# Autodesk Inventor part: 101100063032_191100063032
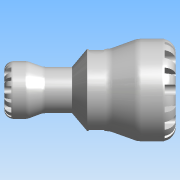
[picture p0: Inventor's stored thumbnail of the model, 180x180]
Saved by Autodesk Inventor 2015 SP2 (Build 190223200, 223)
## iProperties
Created: 2016-12
Part Number: 101100063032_191100063032
Material: PVC-Piping
Description: PLASSON REDUCING COUPLING 63X32 SERIES 1
Document SubType Name: Modeling
Designer: KIM
Mass: 113.204 g
Surface Area: 237.851 cm^2
Volume: 80.8599 cm^3
Density: 1.4 g/cm^3
Appearance: Smooth - White
Author: KIM
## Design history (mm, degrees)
derived "1011.ipt"
feature "Solid1::1011.ipt"
tag "TaggingFeature1"
body "Solid1"
other parameters: "d0" = 172, "d2" = 38.22, "d3" = 63, "d4" = 103, "d5" = 75.6, "d6" = 91, "d7" = 5.25, "d8" = 58, "d9" = 32, "d11" = 23.1, "d12" = 55, "d13" = 2.66667, "d14" = 82.4, "d15" = 46.4, "d16" = 20 deg, "d17" = 20 deg, "d18" = 130 deg, "d22" = 10.96, "d25" = 10.96, "d26" = 0, "d28" = 360 deg, "d30" = 8 deg, "d31" = 1.26, "d32" = 8 deg, "d33" = 1.26, "d35" = 0, "d37" = 360 deg, "d39" = 7.2, "d42" = 7.2, "d43" = 0, "d45" = 360 deg, "d47" = 0.64, "d48" = 8 deg, "d49" = 8 deg, "d50" = 0.64, "d52" = 0, "d54" = 360 deg, "d56" = 11.6, "d57" = 20.6, "d58" = 0.5, "d60" = 12.36, "d61" = 15.75, "d62" = 17.46, "d63" = 0, "d66" = 0, "d68" = 360 deg, "d75" = 9.25585, "d77" = 80.34, "d78" = 1.03, "d_" = 63, "d1" = 32, "E_" = 103, "H_" = 172, "l_" = 91, "E1" = 58, "l1" = 55, "Plasson" = 1, "d20" = 9, "d21" = 13.7, "d23" = 103, "d24" = 75.6, "d40" = 58, "d59" = 18.5117
